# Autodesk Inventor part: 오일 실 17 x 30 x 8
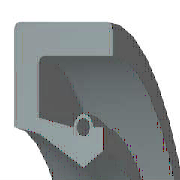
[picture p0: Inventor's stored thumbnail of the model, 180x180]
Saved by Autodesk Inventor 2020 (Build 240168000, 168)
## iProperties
IsCustomPart: 0
Created: 2016-05
Part Number: 오일 실 17 x 30 x 8
Material: 고무
Description: 오일-실
Document SubType Name: Modeling
Standard: KS B 2804
Designer: mduedu
Standards Organization: KS
Language: ko-KR
Size Designation: S - 17 30 8
Categories: <MemberInstance><Categories><Category DisplayName="샤프트 부품" InternalName="7f7aeb1f-a693-4053-b835-cee3144e0d98" Mnemonic="SHFT"><Category DisplayName="실링" Intern
Density: 0.93 g/cm^3
Appearance: 고무 - 검은색 - 버전 1.1
Author: mduedu
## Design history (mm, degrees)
revolve "본체" stored, may be unused: angle "d17" = 90 deg
revolve "스프링1" stored, may be unused: angle "d18" = 90 deg
body "Solid1"
sketch "스케치1"
  geometry: L1 (0, 15)-(8, 15); L2 (8, 15)-(8, 13.75); L3 (8, 13.75)-(1.75, 13.75); L4 (0, 15)-(0, 10.6); L5 (0, 10.6)-(1.75, 10.25); L6 (1.75, 10.25)-(4.9, 8.5); L7 (4.9, 8.5)-(0, 8.5); L8 (6.3, 9.375)-(6.3, 10.6); L9 (0, 0)-(9.586, 0) reference; L10 (4.9, 8.5)-(6.3, 9.375); L11 (0, 18)-(0, -3) reference; L12 (-1.917, 0)-(11.503, 0) reference; L13 (4.2, 10.6)-(1.75, 11.09); L14 (1.75, 11.09)-(1.75, 13.75); L15 (6.3, 10.6)-(5.6, 10.6); C1 r 0.455 at (4.9, 10.6); A1 r 0.7 centre (4.9, 10.6) between (5.6, 10.6) and (4.2, 10.6)
  constraints: 26 end point, 5 horizontal alignment, 4 perpendicular, 2 centre point, 2 collinear, 2 horizontal, 2 parallel, 2 point on circle, 2 point on line, 2 vertical alignment, 1 coincident
  dimensions: "d0" = 30 diameter of L1 L9 (= SD2); "d1" = 18.75 diameter of L8.start L9 (= ABDM); "d2" = 1.25 distance of L1.end L2.end (computed from SD); "d3" = 0.91 diameter of C1 (= SPDI); "d4" = 1.4 diameter of A1 (= SPDA); "d5" = 17 diameter of L6.end L9 (= NND); "d6" = 20.5 diameter of L5.end L9 (= TKDM); "d7" = 21.2 diameter of L4.end L9 (= HLDM); "d8" = 4.9 distance from line of C1.centre L4 (= SPDST); "d9" = 6.3 distance between parallel lines of L8 L4 (= SDI); "d10" = 8 distance between parallel lines of L2 L4 (= SWDT); "d12" = 1.75 distance between parallel lines of L14 L4 (= SD)
fillet "모깎기1" dims "d11" = 0.3 (= RR)
other parameters: "SD2" = 30 [user parameter; used in 1 equation term], "SWDT" = 8 [user parameter; used in 1 equation term], "RR" = 0.3 [user parameter; used in 1 equation term], "SD" = 1.75 [user parameter; used in 2 equation terms], "NND" = 17 [user parameter; used in 1 equation term], "SPDA" = 1.4 [user parameter; used in 1 equation term], "SPDI" = 0.91 [user parameter; used in 1 equation term], "TKDM" = 20.5 [user parameter; used in 1 equation term], "HLDM" = 21.2 [user parameter; used in 1 equation term], "ABDM" = 18.75 [user parameter; used in 1 equation term], "SDI" = 6.3 [user parameter; used in 1 equation term], "SPDST" = 4.9 [user parameter; used in 1 equation term], "d13" = 0, "d14" = 0, "d15" = 0, "LAB" = 0.35 [user parameter]
